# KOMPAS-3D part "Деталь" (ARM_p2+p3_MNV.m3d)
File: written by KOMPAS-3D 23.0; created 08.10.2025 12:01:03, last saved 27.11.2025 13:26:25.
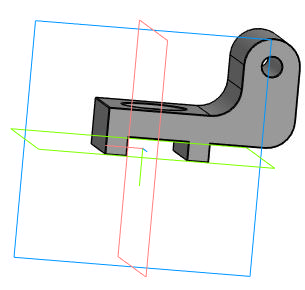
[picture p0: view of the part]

Document properties: Автор: ADMIN; Полное имя файла: D:\YandexDisk\Model\NVG\ARM mkII\ARM p2+p3 MNV.m3d

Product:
- Part/product: Деталь
    Масса: 0.086194

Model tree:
1. Эскиз:1
2. Элемент выдавливания:1
     Расстояние 1 = 25
3. Эскиз:2  (with: Элемент выдавливания:1)
4. Элемент выдавливания:2
5. Эскиз:3  (with: Элемент выдавливания:1, Элемент выдавливания:2)
6. Элемент выдавливания:3
     Расстояние 2 = 1
7. Скругление:1  (with: Элемент выдавливания:1)
     Радиус = 6
8. Фаска:1  (with: Элемент выдавливания:1, Элемент выдавливания:2)
     Угол = 45; Длина 1 = 0.2; Длина 2 = 0.2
